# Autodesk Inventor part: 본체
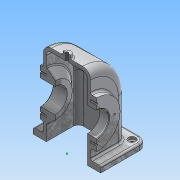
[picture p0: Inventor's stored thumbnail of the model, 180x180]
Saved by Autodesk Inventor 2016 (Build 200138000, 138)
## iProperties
Created: 2018-08
Part Number: 본체
Material: 알루미늄 6061
Document SubType Name: Modeling
Designer: Administrator
Mass: 1092.08 g
Surface Area: 1182.21 cm^2
Volume: 404.475 cm^3
Density: 2.7 g/cm^3
Appearance: 알루미늄 - 평지
Author: Administrator
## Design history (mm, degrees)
sketch "스케치1"
  geometry: L1 (-55, -75)-(55, -75); L2 (55, -75)-(55, 75); L3 (55, 75)-(-55, 75); L4 (-55, 75)-(-55, -75); L5 (-55, -75)-(55, 75); L6 (55, -75)-(-55, 75); 1 further point
  constraints: 12 end point, 2 midpoint, 2 parallel, 1 horizontal, 1 perpendicular
  dimensions: "d0" = 110 distance of L3.end L2.end; "d1" = 150 distance of L2.end L1.end
extrude "돌출1" new body sketch "스케치1" distance "d2" = 10; taper "d3" = 0 deg
sketch "스케치2"
  geometry: L1 (-58, 10)-(58, 10); L2 (58, 10)-(58, 78); L3 (58, 78)-(-58, 78); L4 (-58, 78)-(-58, 10); L5 (-58, 10)-(58, 78); L6 (58, 10)-(-58, 78); L7 (-75, 10)-(75, 10) reference; L8 (-75, 0)-(75, 0) reference; A1 r 58 centre (0, 78) between (58, 78) and (-58, 78); 5 further points
  constraints: 12 end point, 6 midpoint, 2 parallel, 2 point on circle, 2 vertical alignment, 1 centre point, 1 collinear, 1 horizontal, 1 perpendicular
  dimensions: "d4" = 58 radius of A1; "d5" = 78 distance between parallel lines of L8 L3
extrude "돌출2" join sketch "스케치2" stored distance "d6" = 77; taper "d7" = 0 deg
sketch "스케치4"
  geometry: L1 (-52, 0)-(-52, 78); L2 (-52, 78)-(52, 78); L3 (52, 78)-(52, 0); L4 (52, 0)-(-52, 78); L5 (-52, 0)-(52, 78); L6 (-75, 0)-(75, 0) reference; L7 (-52, 0)-(52, 0); A1 r 52 centre (0, 78) between (52, 78) and (-52, 78); 6 further points
  constraints: 12 end point, 7 midpoint, 2 point on circle, 2 vertical alignment, 1 centre point, 1 collinear, 1 parallel
  dimensions: "d17" = 52 radius of A1; "d18" = 78 distance between parallel lines of L6 L2
extrude "돌출3" cut sketch "스케치4" stored distance "d19" = 67; taper "d20" = 0 deg
sketch "스케치3"
  geometry: L1 (-55, 0)-(55, 0) reference; L2 (-38.5, 103)-(-48.5, 103); L3 (-48.5, 103)-(-48.5, 65); L4 (-48.5, 65)-(-38.5, 65); L5 (-38.5, 65)-(-38.5, 103); L6 (-38.5, 10)-(-38.5, 78) reference; L7 (76.84, 65)-(-99.638, 65); 1 further point
  constraints: 10 end point, 2 collinear, 2 horizontal, 2 parallel, 1 perpendicular
  dimensions: "d10" = 10 distance of L2.start L2.end; "d22" = 65 distance between parallel lines of L1 L7
revolve "회전1" sketch "스케치3" stored, may be unused: angle "d11" = 90 deg
sketch "스케치16"
  geometry: L1 (58.026, 65)-(-63.901, 65); L2 (-55, 0)-(55, 0) reference; L3 (19.5, 65)-(43.5, 65); L4 (43.5, 65)-(43.5, 103); L5 (33.5, 104.747)-(19.5, 93); L6 (19.5, 93)-(19.5, 65); L7 (38.5, 78)-(38.5, 136) reference; L8 (33.5, 78)-(33.5, 130) reference; L9 (43.5, 103)-(38.5, 103); L10 (38.5, 104.747)-(33.5, 104.747); L11 (38.5, 104.747)-(38.5, 103); 1 further point
  constraints: 16 end point, 5 point on line, 2 collinear, 2 parallel, 1 horizontal, 1 perpendicular, 1 vertical
  dimensions: "d68" = 65 distance between parallel lines of L2 L1; "d144" = 50 deg angle of L5 L6; "d145" = 56 diameter of L5.end L1; "d147" = 24 distance between parallel lines of L4 L6; "d172" = 5 distance between parallel lines of L4 L7; "d173" = 76 diameter of L9 L1
revolve "회전4" sketch "스케치16" stored, may be unused: angle "d78" = 90 deg
sketch "스케치10"
  geometry: L1 (65.44, 65)-(-67.708, 65); L2 (-55, 0)-(55, 0) reference; L3 (43.5, 85)-(19.5, 85); L4 (19.5, 85)-(19.5, 65); L5 (19.5, 65)-(43.5, 65); L6 (43.5, 65)-(43.5, 85); L7 (-48.5, 103)-(-48.5, 27) reference; L8 (-33.5, 0)-(-33.5, 78) reference; L9 (-48.5, 85)-(-33.5, 85); L10 (-33.5, 85)-(-33.5, 65); L11 (-33.5, 65)-(-48.5, 65); L12 (-48.5, 65)-(-48.5, 85); L13 (38.5, 78)-(38.5, 136) reference; 2 further points
  constraints: 18 end point, 4 parallel, 4 point on line, 3 horizontal, 2 perpendicular
  dimensions: "d30" = 65 distance between parallel lines of L2 L1; "d31" = 40 diameter of L9 L1; "d32" = 40 diameter of L3 L1; "d117" = 5 distance between parallel lines of L6 L13; "d118" = 24 distance between parallel lines of L6 L4
revolve "회전3" sketch "스케치10" stored, may be unused: angle "d34" = 90 deg
node "작업 평면1"
sketch "스케치13"
  geometry: C1 r 6 at (0, 0); 1 further point
  constraints: 1 centre point, 1 coincident
  dimensions: "d48" = 12 diameter of C1
extrude "돌출4" join sketch "스케치13" stored distance "d49" = 67; taper "d50" = 5 deg
hole "구멍1" diameter "d53" = 4.459; stored, may be unused: countersink angle "d57" = 90 deg, drill point angle "d59" = 118 deg; dims "d51" = 10, "d52" = 10, "d54" = 10, "d55" = 4, "d56" = 2, "d58" = 12.8
sketch "스케치14"
  geometry: L1 (0, -74.589)-(0, 82.856); L2 (-91.124, 0)-(91.124, 0); C1 r 20 at (0, 0) reference; C2 r 20 at (0, 0) reference; A1 r 29 centre (0, 0) between (-29, 0) and (0, -29); 4 further points
  constraints: 6 point on line, 4 end point, 4 point on circle, 2 midpoint, 1 centre point, 1 coincident, 1 horizontal, 1 vertical
  dimensions: "d60" = 58 diameter of A1
hole "구멍2" sketch "스케치14" at (-29, 0), (0, -29), (29, 0), (0, 29) diameter "d61" = 3.242; stored, may be unused: countersink angle "d65" = 90 deg, drill point angle "d67" = 118 deg; dims "d62" = 8, "d63" = 4, "d64" = 2, "d66" = 10
fillet "모깎기1" dims "d79" = 13
fillet "모깎기2" dims "d80" = 12
hole "구멍3" diameter "d83" = 5; stored, may be unused: countersink angle "d87" = 90 deg, drill point angle "d89" = 118 deg; dims "d81" = 10, "d82" = 10, "d84" = 8, "d85" = 12, "d86" = 4, "d88" = 10
hole "구멍4" diameter "d92" = 5; stored, may be unused: countersink angle "d96" = 90 deg, drill point angle "d98" = 118 deg; dims "d90" = 10, "d91" = 10, "d93" = 8, "d94" = 12, "d95" = 4, "d97" = 10
hole "구멍5" diameter "d101" = 5; stored, may be unused: countersink angle "d105" = 90 deg, drill point angle "d107" = 118 deg; dims "d99" = 10, "d100" = 10, "d102" = 8, "d103" = 12, "d104" = 4, "d106" = 10
hole "구멍6" diameter "d110" = 5; stored, may be unused: countersink angle "d114" = 90 deg, drill point angle "d116" = 118 deg; dims "d108" = 10, "d109" = 10, "d111" = 8, "d112" = 12, "d113" = 4, "d115" = 10
sketch "스케치19"
  geometry: L1 (-17.5, -78)-(68.5, -78) reference; L2 (-13, 0)-(-13, -68) reference; 2 further points
  constraints: 1 other
  dimensions: "d119" = 40 distance from line of L1 point (25.5, -38); "d120" = 38.5 distance from line of L2 point (25.5, -38)
feature "엠보싱1" sketch "스케치19" dims "d4" = 58, "d5" = 78, "d121" = 0.5, "d122" = 0
fillet "모깎기3" dims "d133" = 3
fillet "모깎기4" dims "d134" = 3
fillet "모깎기6" dims "d136" = 3
fillet "모깎기7" dims "d137" = 3
fillet "모깎기8" dims "d138" = 8
sketch "스케치24"
  geometry: 1 further point
sketch "스케치25"
  geometry: 1 further point
sketch "스케치26"
  geometry: 1 further point
hole "구멍8" diameter "d150" = 40; stored, may be unused: countersink angle "d154" = 90 deg, drill point angle "d156" = 0 deg; dims "d151" = 6, "d152" = 4, "d153" = 2, "d155" = 24, "d178" = 10, "d179" = 10
sketch "스케치27"
  geometry: 1 further point
sketch "스케치28"
  geometry: L1 (0, -73.614)-(0, 79.276); L2 (99.372, 0)-(-92.841, 0); C1 r 20 at (0, 0) reference; C2 r 1.621 at (0, 29) reference; C3 r 1.621 at (29, 0) reference; A1 r 29 centre (0, 0) between (0, -29) and (-29, 0); 3 further points
  constraints: 4 end point, 4 point on line, 3 coincident, 2 point on circle, 1 centre point, 1 horizontal, 1 vertical
  dimensions: "d157" = 58 diameter of A1
hole "구멍9" sketch "스케치28" at (29, 0), (0, -29), (-29, 0), (0, 29) diameter "d158" = 3.242; stored, may be unused: countersink angle "d162" = 90 deg, drill point angle "d164" = 118 deg; dims "d159" = 8, "d160" = 4, "d161" = 2, "d163" = 10
chamfer "모따기1" distance "d165" = 1; stored, may be unused: second distance "d166" = 2, angle "d167" = 45 deg
chamfer "모따기2" distance "d168" = 1; stored, may be unused: second distance "d169" = 2, angle "d170" = 45 deg
fillet "모깎기11" dims "d174" = 3
fillet "모깎기12" dims "d175" = 3
sketch "스케치29"
  geometry: L1 (107.452, 144.221)-(-107.071, 144.221); L2 (-107.071, 144.221)-(-107.071, -22.29); L3 (-107.071, -22.29)-(107.452, -22.29); L4 (107.452, -22.29)-(107.452, 144.221); 1 further point
  constraints: 8 end point, 2 parallel, 1 horizontal, 1 perpendicular
extrude "돌출5" cut sketch "스케치29" stored distance "d176" = 10; taper "d177" = 0 deg
node "솔리드1"
other parameters: "d47" = 142
